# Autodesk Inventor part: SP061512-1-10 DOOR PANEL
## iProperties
Created: 2012-06
Part Number: SP061512-1-10 DOOR PANEL
Material: Polycarbonate, Clear
Document SubType Name: Modeling
Designer: Administrator
Mass: 15150.9 g
Surface Area: 45537.2 cm^2
Volume: 12625.8 cm^3
Density: 1.2 g/cm^3
Author: Administrator
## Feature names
1. Extrusion1
